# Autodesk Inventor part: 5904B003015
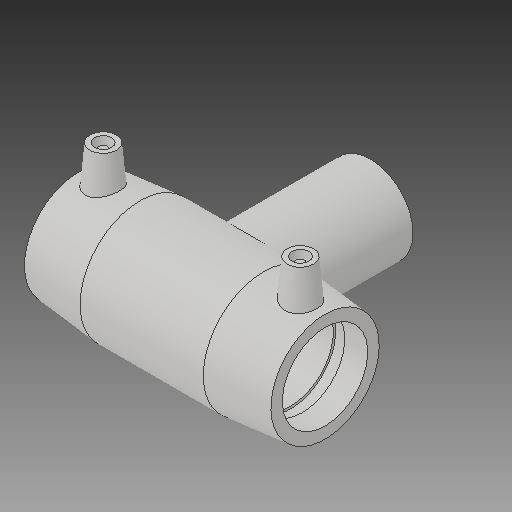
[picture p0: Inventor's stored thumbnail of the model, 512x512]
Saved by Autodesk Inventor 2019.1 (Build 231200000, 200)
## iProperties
Created: 2017-06
Part Number: 5904B003015
Material: Generic
Description: PLASSON TEE 1 1/2''IPS
Document SubType Name: Modeling
Designer: KIM
Mass: 17327.5 g
Surface Area: 12195.1 cm^2
Volume: 17327.5 cm^3
Density: 1 g/cm^3
Appearance: Default
Author: KIM
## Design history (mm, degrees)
derived "5904B.ipt"
feature "Solid1::5904B.ipt"
tag "TaggingFeature1"
body "Solid1"
other parameters: "d0" = 138.938, "d1" = 48.1, "d2" = 67.818, "d3" = 48.514, "d4" = 34.7345, "d5" = 61.0362, "d6" = 45.695, "d7" = 48.1, "d8" = 168 deg, "d10" = 19.4056, "d11" = 6.46853, "d13" = 138.938, "d14" = 17.6296, "d17" = 43.29, "d18" = 48.1, "d19" = 3.52592, "d20" = 168 deg, "d22" = 63.07074, "d23" = 67.818, "d24" = 61.17862, "d25" = 135 deg, "d26" = 97.2566, "d27" = 135 deg, "d29" = 51.816, "d30" = 15, "d31" = 55.5752, "d34" = 5 deg, "d35" = 15, "d39" = 5 deg, "d40" = 9.6, "d41" = 4.8, "d42" = 6, "d43" = 0, "d45" = 4, "d46" = 14, "d47" = 0, "d48" = -94.996, "d49" = 48.1, "d51" = 0, "d52" = 38.48, "d54" = 0, "d55" = 61.0362, "d56" = 67.818, "d57" = 48.6283, "d58" = 135 deg, "d59" = 48.514, "d60" = 48.514, "d61" = 135 deg, "d62" = 94.996, "d72" = 63.21679, "d73" = 31.60839, "d74" = -94.996, "d75" = 50.505, "d77" = 0, "d78" = 38.48, "d80" = 0, "d81" = 48.1, "d82" = 61.087, "d83" = 0, "d84" = 3, "d85" = 0, "d86" = 3, "d87" = 0, "d88" = 14.06906, "d89" = 3.51727, "d90" = 14.06906, "d_" = 48.1, "L_" = 138.938, "L_1" = 48.514, "D_" = 67.818, "A_" = 51.816, "d_2" = 12, "H_" = 94.996
